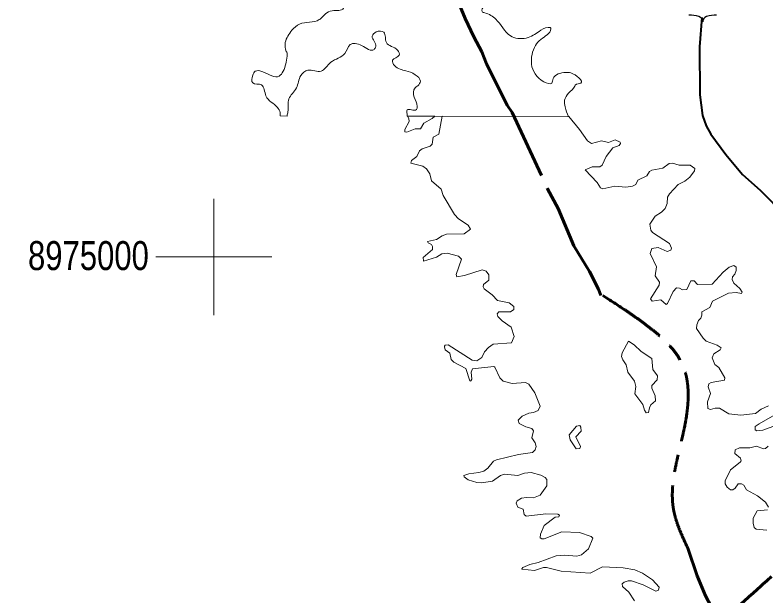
# Model space of a CAD drawing. Extents: x -1643653 to 4543381, y 1624270 to 13878484.
# Drawn here: x 571573 to 584514, y 8969158 to 8979171 of the extents above; entities that cross this region are included whole.
import ezdxf
from ezdxf.enums import TextEntityAlignment as Align

# ---------------------------------------------------------------- set-up
doc = ezdxf.new("R2010")
doc.units = 0
doc.header["$LTSCALE"] = 200
doc.linetypes.add('LONG_DASH_SHORT_DASH', pattern=[9.9, 6, -1.2, 1.5, -1.2])
for name, color, linetype, lineweight in [('12', 7, 'Continuous', 25), ('2', 7, 'Continuous', 13), ('25', 7, 'Continuous', 13), ('48', 7, 'Continuous', 25), ('60', 7, 'Continuous', 13), ('7', 7, 'LONG_DASH_SHORT_DASH', 60)]:
    doc.layers.add(name, color=color, linetype=linetype, lineweight=lineweight)
doc.layers.add('47', color=7, linetype='Continuous')

msp = doc.modelspace()

# ---------------------------------------------------------------- linework, layer by layer
at = {"layer": '12', "lineweight": 40}
msp.add_lwpolyline([(583409.2, 8979126), (583370.9, 8978624.6), (583373.1, 8977794.5), (583422.7, 8977439.4), (583485.5, 8977258.4), (583563.7, 8977119.5), (583820.7, 8976765.3), (584108.1, 8976423.9), (584414.4, 8976152.1), (584852.4, 8975709.9)], dxfattribs=at)
at = {"layer": '2'}
for p, q in [((575000, 8974000), (575000, 8976000)), ((574000, 8975000), (576000, 8975000))]:
    msp.add_line(p, q, dxfattribs=at)
at = {"layer": '25'}
for p, q in [((576139.8, 8977430.2), (576260.1, 8977429.9)), ((578329.8, 8977426), (581113.2, 8977420.6)), ((578932.9, 8977424.8), (581114.7, 8977420.6)), ((581097.2, 8977420.6), (581114.7, 8977420.6))]:
    msp.add_line(p, q, dxfattribs=at)
for points in [[(578807.8, 8977425), (578762, 8977384.2), (578616.1, 8977306), (578558.4, 8977210.3), (578467, 8977210.1), (578327, 8977150.7), (578293.1, 8977159.1), (578290.8, 8977197.4), (578364.9, 8977333.4), (578357, 8977384.6), (578337.1, 8977425.9), (578807.8, 8977425)], [(582256.6, 8972639), (582390.4, 8972456), (582418.2, 8972362.6), (582451.8, 8972314.2), (582490.4, 8972318.2), (582505.3, 8972400.8), (582532.7, 8972449.4), (582611.3, 8972522), (582607.1, 8972609.2), (582549.8, 8972736.7), (582547.7, 8972782.9), (582638.8, 8972882.9), (582643.2, 8972950.8), (582566.8, 8973059.6), (582547.5, 8973252.7), (582365, 8973371.6), (582241.8, 8973488.4), (582144.3, 8973552.1), (582036.5, 8973349.9), (582027.3, 8973284.3), (582048.5, 8973225.1), (582105.8, 8973144.3), (582131.1, 8973013.1), (582248.1, 8972859.9), (582269.4, 8972766)], [(582256.6, 8972639), (582390.4, 8972456), (582418.2, 8972362.6), (582451.8, 8972314.2), (582490.4, 8972318.2), (582505.3, 8972400.8), (582532.7, 8972449.4), (582611.3, 8972522), (582607.1, 8972609.2), (582549.8, 8972736.7), (582547.7, 8972782.9), (582638.8, 8972882.9), (582643.2, 8972950.8), (582566.8, 8973059.6), (582547.5, 8973252.7), (582365, 8973371.6), (582241.8, 8973488.4), (582144.3, 8973552.1), (582036.5, 8973349.9), (582027.3, 8973284.3), (582048.5, 8973225.1), (582105.8, 8973144.3), (582131.1, 8973013.1), (582248.1, 8972859.9), (582269.4, 8972766)], [(581237.1, 8971901.1), (581328.3, 8971997.6), (581324, 8972069.6), (581307.2, 8972094.7), (581247.3, 8972081.7), (581124.6, 8971937.6), (581139.6, 8971848.2), (581245.5, 8971693.7), (581304.9, 8971699.9), (581317.6, 8971731.5)], [(581237.1, 8971901.1), (581328.3, 8971997.6), (581324, 8972069.6), (581307.2, 8972094.7), (581247.3, 8972081.7), (581124.6, 8971937.6), (581139.6, 8971848.2), (581245.5, 8971693.7), (581304.9, 8971699.9), (581317.6, 8971731.5)]]:
    msp.add_lwpolyline(points, close=True, dxfattribs=at)
for points in [[(578611.4, 8974932.3), (578606.9, 8974988.9), (578766.5, 8975126.6), (578766.4, 8975183.8), (578747.5, 8975213.1), (578690.1, 8975245.3), (578681.8, 8975268.5), (578836.8, 8975302.7), (578932.2, 8975366.2), (579010.6, 8975391.7), (579312.2, 8975398.2), (579422.7, 8975479.2), (579384.5, 8975547), (579214.9, 8975657.2), (579145.2, 8975733), (578951.3, 8976060.9), (578917.2, 8976171.5), (578917.2, 8976171.5), (578749.8, 8976313.4), (578719.8, 8976432.4), (578664.5, 8976519.7), (578597.9, 8976566.7), (578392.8, 8976615.1), (578404.8, 8976660.8), (578496.7, 8976734.3), (578545.8, 8976827.9), (578588.3, 8976861.8), (578728.9, 8976909.1), (578762.2, 8976944.9), (578777.1, 8977063.3), (578874.7, 8977114.7), (578932.9, 8977424.8)], [(578611.4, 8974932.3), (578606.9, 8974988.9), (578766.5, 8975126.6), (578766.4, 8975183.8), (578747.5, 8975213.1), (578690.1, 8975245.3), (578681.8, 8975268.5), (578836.8, 8975302.7), (578932.2, 8975366.2), (579010.6, 8975391.7), (579312.2, 8975398.2), (579422.7, 8975479.2), (579384.5, 8975547), (579214.9, 8975657.2), (579145.2, 8975733), (578951.3, 8976060.9), (578917.2, 8976171.5), (578917.2, 8976171.5), (578749.8, 8976313.4), (578719.8, 8976432.4), (578664.5, 8976519.7), (578597.9, 8976566.7), (578392.8, 8976615.1), (578404.8, 8976660.8), (578496.7, 8976734.3), (578545.8, 8976827.9), (578588.3, 8976861.8), (578728.9, 8976909.1), (578762.2, 8976944.9), (578777.1, 8977063.3), (578874.7, 8977114.7), (578932.9, 8977424.8)], [(581114.7, 8977420.6), (581302.8, 8977195.3), (581439, 8977003.9), (581505.2, 8976955.2), (581681.2, 8977004.1), (581802.3, 8976974.5), (581916.8, 8977021), (582001.7, 8976980.5), (582005.8, 8976956.9), (581984.9, 8976923.6), (581874.3, 8976882.9), (581757.5, 8976730.1), (581691.6, 8976583.6), (581652.6, 8976555.8), (581521.7, 8976555.8), (581398.7, 8976500.6), (581602.4, 8976283.9), (581662.1, 8976192.6), (581662.1, 8976192.6), (581700.3, 8976175.7), (581908, 8976220.2), (582099.5, 8976201.1), (582214.4, 8976220.3), (582271.4, 8976250.1), (582307.6, 8976324.1), (582458.4, 8976398.8), (582508, 8976475.6), (582547.4, 8976498.9), (582737, 8976528.4), (582843.2, 8976613.2), (582902.4, 8976617.4), (583015.7, 8976581.5), (583207.5, 8976583.6), (583288.9, 8976528.1), (583288.8, 8976526.9)], [(581114.7, 8977420.6), (581302.8, 8977195.3), (581439, 8977003.9), (581505.2, 8976955.2), (581681.2, 8977004.1), (581802.3, 8976974.5), (581916.8, 8977021), (582001.7, 8976980.5), (582005.8, 8976956.9), (581984.9, 8976923.6), (581874.3, 8976882.9), (581757.5, 8976730.1), (581691.6, 8976583.6), (581652.6, 8976555.8), (581521.7, 8976555.8), (581398.7, 8976500.6), (581602.4, 8976283.9), (581662.1, 8976192.6), (581662.1, 8976192.6), (581700.3, 8976175.7), (581908, 8976220.2), (582099.5, 8976201.1), (582214.4, 8976220.3), (582271.4, 8976250.1), (582307.6, 8976324.1), (582458.4, 8976398.8), (582508, 8976475.6), (582547.4, 8976498.9), (582737, 8976528.4), (582843.2, 8976613.2), (582902.4, 8976617.4), (583015.7, 8976581.5), (583207.5, 8976583.6), (583288.9, 8976528.1), (583288.8, 8976526.9)], [(583288.8, 8976526.9), (583284.2, 8976482.2), (583201.7, 8976377.2), (583115.1, 8976307.5), (583002.1, 8976249.7), (582849.4, 8976088.5), (582817.5, 8976033.3), (582808.9, 8975922.8), (582779.2, 8975835.8), (582715.7, 8975774.3), (582605.1, 8975701.9), (582513.8, 8975564), (582530.6, 8975464.3), (582556.2, 8975419.4), (582849.3, 8975232.4), (582883.3, 8975154.1), (582874.6, 8975119.8), (582813, 8975092.3), (582657.9, 8975162.3), (582549.9, 8975147.4), (582515.9, 8975060.4), (582630.4, 8974832.8), (582607.2, 8974673.8), (582681.4, 8974567.3), (582672.8, 8974512.1), (582526.5, 8974278.7), (582552.2, 8974236.2), (582705.1, 8974259.4), (582796.4, 8974181.2), (582819.6, 8974200.3), (582913.3, 8974404.2), (582970, 8974469.5), (583025.6, 8974463.4), (583073.1, 8974433.7), (583150.7, 8974442.2), (583217.8, 8974586.7), (583276, 8974590.8), (583333.9, 8974527.2), (583584.3, 8974533.6), (583775.5, 8974739.6), (583881.7, 8974826.7), (583962.1, 8974856.3), (583998.4, 8974822.4), (584002.7, 8974769.4), (583977.2, 8974705.7), (583934.9, 8974658.8), (583930.7, 8974609.8), (583962.6, 8974546.2), (584062, 8974459.3), (584101.2, 8974395.9), (584094.7, 8974371.5)], [(583288.8, 8976526.9), (583284.2, 8976482.2), (583201.7, 8976377.2), (583115.1, 8976307.5), (583002.1, 8976249.7), (582849.4, 8976088.5), (582817.5, 8976033.3), (582808.9, 8975922.8), (582779.2, 8975835.8), (582715.7, 8975774.3), (582605.1, 8975701.9), (582513.8, 8975564), (582530.6, 8975464.3), (582556.2, 8975419.4), (582849.3, 8975232.4), (582883.3, 8975154.1), (582874.6, 8975119.8), (582813, 8975092.3), (582657.9, 8975162.3), (582549.9, 8975147.4), (582515.9, 8975060.4), (582630.4, 8974832.8), (582607.2, 8974673.8), (582681.4, 8974567.3), (582672.8, 8974512.1), (582526.5, 8974278.7), (582552.2, 8974236.2), (582705.1, 8974259.4), (582796.4, 8974181.2), (582819.6, 8974200.3), (582913.3, 8974404.2), (582970, 8974469.5), (583025.6, 8974463.4), (583073.1, 8974433.7), (583150.7, 8974442.2), (583217.8, 8974586.7), (583276, 8974590.8), (583333.9, 8974527.2), (583584.3, 8974533.6), (583775.5, 8974739.6), (583881.7, 8974826.7), (583962.1, 8974856.3), (583998.4, 8974822.4), (584002.7, 8974769.4), (583977.2, 8974705.7), (583934.9, 8974658.8), (583930.7, 8974609.8), (583962.6, 8974546.2), (584062, 8974459.3), (584101.2, 8974395.9), (584094.7, 8974371.5)], [(578975.1, 8973452.6), (578973.3, 8973461.4), (578982.8, 8973480.8), (579038.7, 8973488.1), (579452.5, 8973223.1), (579529.1, 8973212.4), (579617.1, 8973270.5), (579663.1, 8973365.4), (579733.3, 8973441.9), (579814, 8973499.2), (580130.2, 8973518.3), (580172.7, 8973628.6), (580121.6, 8973788.1), (579968.9, 8973900.6), (579894.7, 8973976.9), (579879.7, 8974019.7), (579911.8, 8974055.6), (580113, 8974056.4), (580170.5, 8974093.8), (580166.7, 8974144.9), (580087.5, 8974208.6), (579890.3, 8974249), (579794.6, 8974346.6), (579656.5, 8974453.1), (579639.6, 8974487), (579648.1, 8974525.1), (579737.1, 8974599.3), (579739.4, 8974695), (579694.8, 8974754.5), (579622.3, 8974777.8), (579316.9, 8974682.4), (579184.6, 8974659.3), (579172.4, 8974699.5), (579265.5, 8974960.7), (579214.4, 8975011.6), (579019.1, 8975068.8), (578930.3, 8975051.9), (578836.6, 8974994.6), (578611.5, 8974931), (578611.4, 8974932.3)], [(578975.1, 8973452.6), (578973.3, 8973461.4), (578982.8, 8973480.8), (579038.7, 8973488.1), (579452.5, 8973223.1), (579529.1, 8973212.4), (579617.1, 8973270.5), (579663.1, 8973365.4), (579733.3, 8973441.9), (579814, 8973499.2), (580130.2, 8973518.3), (580172.7, 8973628.6), (580121.6, 8973788.1), (579968.9, 8973900.6), (579894.7, 8973976.9), (579879.7, 8974019.7), (579911.8, 8974055.6), (580113, 8974056.4), (580170.5, 8974093.8), (580166.7, 8974144.9), (580087.5, 8974208.6), (579890.3, 8974249), (579794.6, 8974346.6), (579656.5, 8974453.1), (579639.6, 8974487), (579648.1, 8974525.1), (579737.1, 8974599.3), (579739.4, 8974695), (579694.8, 8974754.5), (579622.3, 8974777.8), (579316.9, 8974682.4), (579184.6, 8974659.3), (579172.4, 8974699.5), (579265.5, 8974960.7), (579214.4, 8975011.6), (579019.1, 8975068.8), (578930.3, 8975051.9), (578836.6, 8974994.6), (578611.5, 8974931), (578611.4, 8974932.3)], [(584094.7, 8974371.5), (584094.1, 8974369.4), (584000.2, 8974389.1), (583871.1, 8974374.2), (583595, 8974238.2), (583546.1, 8974127.9), (583408, 8974057.7), (583410, 8973996.2), (583390.8, 8973947.2), (583350.4, 8973904.1), (583321, 8973828.3), (583316.7, 8973767.3), (583431.6, 8973598.8), (583482.4, 8973550.1), (583671.6, 8973479.8), (583743.5, 8973435.3), (583724.3, 8973401.2), (583613.9, 8973333.2), (583584.4, 8973263.3), (583634.8, 8973145.1), (583699.1, 8973095.2), (583807.2, 8972917.2), (583799, 8972879.6), (583569.4, 8972838.4), (583527, 8972815), (583518.6, 8972761.7), (583556.6, 8972647.5), (583505.6, 8972506.1), (583512.2, 8972386.1), (583560.7, 8972371.1), (583638.2, 8972394.5), (583713.6, 8972394.5), (583875.1, 8972294.7), (584079, 8972273.4), (584331.8, 8972301), (584432.1, 8972379.7), (584559.6, 8972432.7)], [(584094.7, 8974371.5), (584094.1, 8974369.4), (584000.2, 8974389.1), (583871.1, 8974374.2), (583595, 8974238.2), (583546.1, 8974127.9), (583408, 8974057.7), (583410, 8973996.2), (583390.8, 8973947.2), (583350.4, 8973904.1), (583321, 8973828.3), (583316.7, 8973767.3), (583431.6, 8973598.8), (583482.4, 8973550.1), (583671.6, 8973479.8), (583743.5, 8973435.3), (583724.3, 8973401.2), (583613.9, 8973333.2), (583584.4, 8973263.3), (583634.8, 8973145.1), (583699.1, 8973095.2), (583807.2, 8972917.2), (583799, 8972879.6), (583569.4, 8972838.4), (583527, 8972815), (583518.6, 8972761.7), (583556.6, 8972647.5), (583505.6, 8972506.1), (583512.2, 8972386.1), (583560.7, 8972371.1), (583638.2, 8972394.5), (583713.6, 8972394.5), (583875.1, 8972294.7), (584079, 8972273.4), (584331.8, 8972301), (584432.1, 8972379.7), (584559.6, 8972432.7)], [(579428.2, 8972865), (579426, 8972861.6), (579411.7, 8972863.7), (579339.8, 8973076.5), (579133.8, 8973184.9), (579087.3, 8973233.8), (579065.8, 8973339.9), (578985.3, 8973401.7), (578975.1, 8973452.6)], [(579428.2, 8972865), (579426, 8972861.6), (579411.7, 8972863.7), (579339.8, 8973076.5), (579133.8, 8973184.9), (579087.3, 8973233.8), (579065.8, 8973339.9), (578985.3, 8973401.7), (578975.1, 8973452.6)], [(579310.3, 8971213.6), (579305.7, 8971235), (579395.2, 8971264.1), (579567.6, 8971283.5), (579652.3, 8971309), (579720.3, 8971360), (579820.2, 8971478.9), (579869.2, 8971504.5), (580251.6, 8971593.7), (580491.5, 8971629.9), (580538.3, 8971676.8), (580555.1, 8971736.2), (580536, 8971797.3), (580480.8, 8971882.8), (580506.2, 8972005.7), (580476.5, 8972043.8), (580374.6, 8972073.7), (580260.5, 8972130.7), (580245.1, 8972188.4), (580313.2, 8972254.3), (580427.7, 8972309.4), (580506.2, 8972318.1), (580588.8, 8972354), (580625.2, 8972430.6), (580529.8, 8972659.8), (580429.6, 8972808.8), (580370.3, 8972836.3), (580141.2, 8972817.2), (579988, 8972861.8), (579925.9, 8972916.6), (579843.7, 8973099.2), (579822.5, 8973110.2), (579456.8, 8973074), (579433.6, 8973012.6), (579446.1, 8972893.7), (579428.2, 8972865)], [(579310.3, 8971213.6), (579305.7, 8971235), (579395.2, 8971264.1), (579567.6, 8971283.5), (579652.3, 8971309), (579720.3, 8971360), (579820.2, 8971478.9), (579869.2, 8971504.5), (580251.6, 8971593.7), (580491.5, 8971629.9), (580538.3, 8971676.8), (580555.1, 8971736.2), (580536, 8971797.3), (580480.8, 8971882.8), (580506.2, 8972005.7), (580476.5, 8972043.8), (580374.6, 8972073.7), (580260.5, 8972130.7), (580245.1, 8972188.4), (580313.2, 8972254.3), (580427.7, 8972309.4), (580506.2, 8972318.1), (580588.8, 8972354), (580625.2, 8972430.6), (580529.8, 8972659.8), (580429.6, 8972808.8), (580370.3, 8972836.3), (580141.2, 8972817.2), (579988, 8972861.8), (579925.9, 8972916.6), (579843.7, 8973099.2), (579822.5, 8973110.2), (579456.8, 8973074), (579433.6, 8973012.6), (579446.1, 8972893.7), (579428.2, 8972865)], [(584785.8, 8972347.3), (584395, 8972126.3), (584330, 8972075.8), (584330, 8972018.8), (584357.8, 8972001.5), (584461.6, 8972014.2), (584630.9, 8972080)], [(584785.8, 8972347.3), (584395, 8972126.3), (584330, 8972075.8), (584330, 8972018.8), (584357.8, 8972001.5), (584461.6, 8972014.2), (584630.9, 8972080)], [(584552.9, 8971738.1), (584503.4, 8971697.7), (584472.4, 8971696.2), (584351.2, 8971742.2), (584236.4, 8971708.4), (584057.5, 8971710.4), (583985.8, 8971674.1), (583977.4, 8971610.7), (584075.1, 8971531.8), (584087.7, 8971489.6), (584070.5, 8971461.8), (583900.8, 8971334.4), (583811.7, 8971141.1), (583811.7, 8971092.1), (583843.3, 8971033.3), (583905.1, 8970986.2), (583943.3, 8970988.3), (583985.6, 8971013.6), (584034.9, 8971088), (584092, 8971088), (584134.5, 8971066.8), (584177.1, 8970988.3), (584368.2, 8970884.1), (584506.1, 8970773.8), (584557, 8970686.9)], [(584552.9, 8971738.1), (584503.4, 8971697.7), (584472.4, 8971696.2), (584351.2, 8971742.2), (584236.4, 8971708.4), (584057.5, 8971710.4), (583985.8, 8971674.1), (583977.4, 8971610.7), (584075.1, 8971531.8), (584087.7, 8971489.6), (584070.5, 8971461.8), (583900.8, 8971334.4), (583811.7, 8971141.1), (583811.7, 8971092.1), (583843.3, 8971033.3), (583905.1, 8970986.2), (583943.3, 8970988.3), (583985.6, 8971013.6), (584034.9, 8971088), (584092, 8971088), (584134.5, 8971066.8), (584177.1, 8970988.3), (584368.2, 8970884.1), (584506.1, 8970773.8), (584557, 8970686.9)], [(580309.7, 8969624.7), (580324.1, 8969646.6), (580442.8, 8969703), (580591, 8969734.8), (580897.4, 8969851.8), (581049.8, 8969860.2), (581253.8, 8969843.2), (581332.8, 8969868.9), (581457.9, 8969968.6), (581532.1, 8970155.4), (581503.8, 8970183.4), (581300.7, 8970253.2), (580995.1, 8970263.8), (580689.2, 8970142.9), (580650.8, 8970142.8), (580623.4, 8970161.8), (580627.3, 8970223.2), (580693.7, 8970370.5), (580880.2, 8970516.6), (580943.8, 8970521), (580954.3, 8970548.4), (580926, 8970569.8), (580722.7, 8970576.1), (580378.8, 8970531.6), (580349, 8970559.3), (580332.1, 8970654.5), (580240.8, 8970690.9), (580211.1, 8970756.7), (580226.1, 8970795), (580302.3, 8970841.6), (580387.3, 8970856.5), (580506.2, 8970848.1), (580624.5, 8970894.4), (580735.6, 8971058.1), (580739.9, 8971163.9), (580708, 8971200.6), (580633.5, 8971239), (580468.3, 8971285.6), (580353.1, 8971277.1), (580237.8, 8971236.7), (580009, 8971255.8), (579937.2, 8971232.5), (579937.2, 8971232.5), (579800.8, 8971134.7), (579609.6, 8971107.2), (579533.4, 8971111.5), (579380.7, 8971160.2), (579310.3, 8971213.6)], [(580309.7, 8969624.7), (580324.1, 8969646.6), (580442.8, 8969703), (580591, 8969734.8), (580897.4, 8969851.8), (581049.8, 8969860.2), (581253.8, 8969843.2), (581332.8, 8969868.9), (581457.9, 8969968.6), (581532.1, 8970155.4), (581503.8, 8970183.4), (581300.7, 8970253.2), (580995.1, 8970263.8), (580689.2, 8970142.9), (580650.8, 8970142.8), (580623.4, 8970161.8), (580627.3, 8970223.2), (580693.7, 8970370.5), (580880.2, 8970516.6), (580943.8, 8970521), (580954.3, 8970548.4), (580926, 8970569.8), (580722.7, 8970576.1), (580378.8, 8970531.6), (580349, 8970559.3), (580332.1, 8970654.5), (580240.8, 8970690.9), (580211.1, 8970756.7), (580226.1, 8970795), (580302.3, 8970841.6), (580387.3, 8970856.5), (580506.2, 8970848.1), (580624.5, 8970894.4), (580735.6, 8971058.1), (580739.9, 8971163.9), (580708, 8971200.6), (580633.5, 8971239), (580468.3, 8971285.6), (580353.1, 8971277.1), (580237.8, 8971236.7), (580009, 8971255.8), (579937.2, 8971232.5), (579937.2, 8971232.5), (579800.8, 8971134.7), (579609.6, 8971107.2), (579533.4, 8971111.5), (579380.7, 8971160.2), (579310.3, 8971213.6)], [(584540.2, 8970639.9), (584364.7, 8970623), (584293.8, 8970497.2), (584291.7, 8970412.5), (584311, 8970338.1), (584347.1, 8970310.6), (584528.8, 8970293.7)], [(584540.2, 8970639.9), (584364.7, 8970623), (584293.8, 8970497.2), (584291.7, 8970412.5), (584311, 8970338.1), (584347.1, 8970310.6), (584528.8, 8970293.7)], [(582248.2, 8969074.3), (582148.5, 8969222.7), (582042.2, 8969318.6), (582035.8, 8969367.1), (582067.6, 8969395), (582142, 8969420.5), (582195.2, 8969417.7), (582396.8, 8969348.3), (582613.7, 8969237.8), (582662.3, 8969257), (582672.9, 8969307.9), (582558.3, 8969437.5), (582387.3, 8969552.8), (582256.4, 8969609.6), (582053, 8969641.4), (581695.9, 8969662.6), (581486.8, 8969550.1), (580986.3, 8969586.2), (580731.4, 8969647.8), (580680.5, 8969647.7), (580527.5, 8969596.8), (580305.1, 8969617.7), (580309.7, 8969624.7)], [(582248.2, 8969074.3), (582148.5, 8969222.7), (582042.2, 8969318.6), (582035.8, 8969367.1), (582067.6, 8969395), (582142, 8969420.5), (582195.2, 8969417.7), (582396.8, 8969348.3), (582613.7, 8969237.8), (582662.3, 8969257), (582672.9, 8969307.9), (582558.3, 8969437.5), (582387.3, 8969552.8), (582256.4, 8969609.6), (582053, 8969641.4), (581695.9, 8969662.6), (581486.8, 8969550.1), (580986.3, 8969586.2), (580731.4, 8969647.8), (580680.5, 8969647.7), (580527.5, 8969596.8), (580305.1, 8969617.7), (580309.7, 8969624.7)]]:
    msp.add_lwpolyline(points, dxfattribs=at)
for points in [[(581113.2, 8977420.6), (581052, 8977586.8), (581044.4, 8977701), (581112.9, 8977822.7), (581219.3, 8977944.5), (581226.9, 8977959.7), (581325.8, 8977997.7), (581150.9, 8978172.7), (581059.6, 8978180.3), (580846.7, 8978073.8), (580823.9, 8977997.7), (580687, 8978020.5), (580474.1, 8978324.9), (580542.6, 8978644.5), (580633.8, 8978751), (580808.7, 8978933.6), (580808.7, 8978941.2), (580763.1, 8978956.4), (580603.4, 8978888), (580382.9, 8978773.8), (580109.1, 8978811.9), (579858.2, 8979101), (579668.1, 8979207.5), (579622.5, 8979230.4), (579622.5, 8979276), (579736.5, 8979359.7), (579827.8, 8979539.3), (579843, 8979691.5), (579827.8, 8979881.7), (579934.2, 8980049.1), (580162.3, 8980224.1), (580268.8, 8980246.9), (580337.2, 8980376.3), (580489.3, 8980460), (580595.8, 8980543.7), (580580.6, 8980650.2), (580413.3, 8980627.4), (580246, 8980619.8), (580124.3, 8980642.6), (580154.7, 8980779.6), (580626.2, 8980848), (580755.5, 8980810), (580899.9, 8980939.3), (581006.4, 8981023), (581485.5, 8981030.6), (581667.9, 8981061.1), (581765.3, 8981228.5), (581468.7, 8981160), (581309, 8981236.1), (581187.4, 8981220.9), (581187.4, 8981335), (581073.3, 8981327.4), (580989.7, 8981289.3), (580852.8, 8981297), (580701.6, 8981295.5)], [(577632.4, 8980778.5), (577561.8, 8980643.3), (577493.4, 8980521.6), (577447.7, 8980460.7), (577234.8, 8980529.2), (577120.8, 8980498.8), (577075.1, 8980559.6), (576983.9, 8980574.8), (576679.7, 8980825.9), (576603.7, 8980886.8), (576542.8, 8980879.2), (576489.6, 8980833.5), (576542.8, 8980780.3), (576679.7, 8980711.8), (576961.1, 8980361.8), (577128.4, 8980186.8), (577250, 8979973.7), (577310.9, 8979814), (577508.6, 8979654.2), (577531.4, 8979585.7), (577531.4, 8979555.2), (577371.7, 8979616.1), (577265.2, 8979631.3), (577136, 8979547.6), (577136, 8979479.2), (577151.2, 8979433.5), (577234.8, 8979380.2), (577234.8, 8979288.9), (577037.1, 8979243.3), (576923.1, 8979190), (576862.2, 8979129.2), (576816.6, 8979091.1), (576474.4, 8979015), (576345.2, 8978908.5), (576231.1, 8978695.4), (576246.3, 8978543.3), (576261.5, 8978512.8), (576261.5, 8978459.6), (576193.1, 8978200.9), (576124.6, 8978117.2), (575843.3, 8978193.3), (575714, 8978200.9), (575668.4, 8978132.4), (575668.4, 8978003), (575820.5, 8977965), (575896.5, 8977777.1), (575987.8, 8977670.5), (576094.2, 8977579.2), (576139.8, 8977487.9), (576139.8, 8977430.2)], [(576260.1, 8977429.9), (576276.7, 8977503.1), (576291.9, 8977723.8), (576421.2, 8977914), (576497.2, 8978127.1), (576618.9, 8978218.4), (576847, 8978203.2), (577014.3, 8978355.3), (577257.6, 8978507.5), (577348.9, 8978659.7), (577546.6, 8978644.5), (577759.5, 8978576), (577789.9, 8978629.2), (577729.1, 8978804.3), (577797.5, 8978880.3), (577926.8, 8978872.7), (577972.4, 8978697.7), (578170.1, 8978560.8), (578192.9, 8978477.1), (578078.9, 8978393.4), (578116.9, 8978294.5), (578307, 8978210.8), (578466.7, 8978142.3), (578557.9, 8978028.2), (578512.3, 8977952.1), (578466.7, 8977914), (578451.5, 8977754.2), (578504.7, 8977594.4), (578489.5, 8977541.2), (578329.8, 8977533.6), (578329.8, 8977465.1), (578329.8, 8977426)]]:
    msp.add_spline(points, degree=3, dxfattribs=at)
at = {"layer": '48'}
for centre, radius, start, end in [((583184.3, 8978580.8), 589.7, 72.89371, 89.90057), ((583664.6, 8978580.8), 589.7, 90.09943, 107.10629), ((583330.1, 8979054.2), 94.4, 357.69345, 72.92955), ((583518.8, 8979054.2), 94.4, 107.07045, 182.30655)]:
    msp.add_arc(centre, radius, start, end, dxfattribs=at)
at = {"layer": '60', "lineweight": 25}
msp.add_spline([(814781, 9009175.5), (814787.2, 9009173.4), (814796.9, 9009173.4), (814799.4, 9009172.4), (814805.1, 9009174.5), (814805.6, 9009176.5), (814811.7, 9009179.5), (814811.7, 9009179.5), (814801.5, 9009181), (814790.7, 9009181.5), (814784.1, 9009183.1), (814777.4, 9009185.1), (814778.4, 9009175.5)], degree=3, dxfattribs=at)
at = {"layer": '7'}
for points in [[(579193.1, 8979451.5), (579330.6, 8979113.2), (579479.8, 8978793), (579620.2, 8978538.1), (579698.1, 8978330.6), (580056.8, 8977617.4), (580139.1, 8977491.6), (580748.7, 8976177.5), (580932.4, 8975835.9), (581202.8, 8975191.5), (581475, 8974750.7), (581628.9, 8974447.2), (581670.5, 8974336.1)], [(583174.4, 8969966), (583327.9, 8969505.4), (583474.7, 8969160.4), (583725.5, 8968684.8), (583883.2, 8968539.9), (583982.9, 8968403.5), (584146.9, 8968235.1), (584624.8, 8967616.6), (584992.2, 8967072.1), (585186.8, 8966825.7), (585377.2, 8966655.9), (585748.8, 8966438.6), (585960.5, 8966257.3), (586351.6, 8965976.8), (586551, 8965796.4), (587006.6, 8965310.9), (587303.1, 8964815.2), (587426.7, 8964495.3)]]:
    msp.add_lwpolyline(points, dxfattribs=at)
for points in [[(581705.4, 8974333.7), (582461.9, 8973819.1), (583080, 8973133.9), (583131.7, 8972182.4), (582921.5, 8970648.2), (583174.4, 8969966)], [(583719.8, 8968683.1), (584226, 8969147.1), (585263.8, 8970159.6), (585803.8, 8970817.7), (586453.4, 8971391.4), (587077.8, 8971939.8), (587744.3, 8972277.3), (588469.9, 8972403.9), (588728.8, 8972391.8)]]:
    msp.add_spline(points, degree=3, dxfattribs=at)

# ---------------------------------------------------------------- texts
at = {"layer": '47', "width": 0.8}
msp.add_text('8975000', height=500, dxfattribs=at).set_placement((572837.8, 8974774.3), align=Align.CENTER)

doc.saveas('drawing.dxf')
